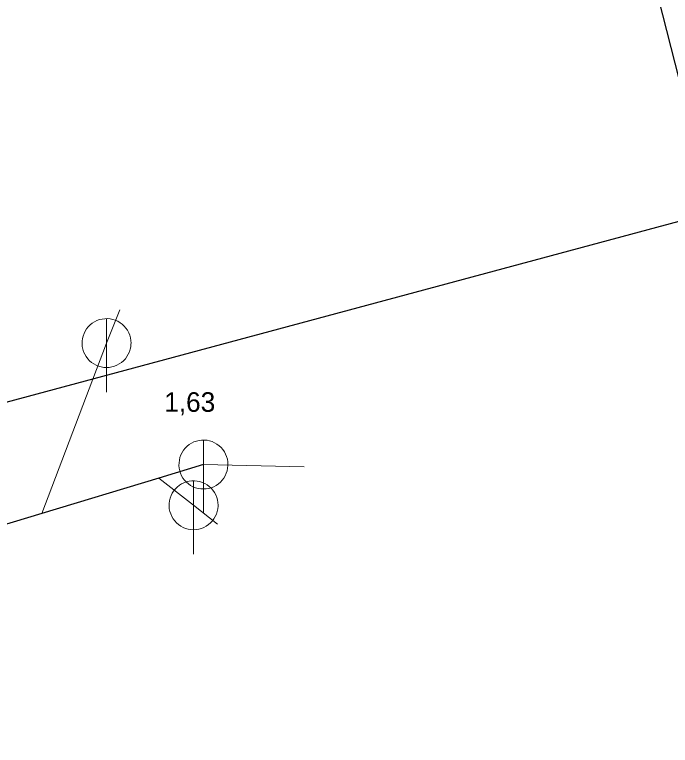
# Model space of a CAD drawing. Extents: x -682839 to -682312, y -994645 to -993949.
# Drawn here: x -682713.06 to -682686.28, y -994200.26 to -994170.41 of the extents above; entities that cross this region are included whole.
import ezdxf

# ---------------------------------------------------------------- set-up
doc = ezdxf.new("R2010")
doc.units = 0
doc.header["$LTSCALE"] = 0.4
doc.layers.add('1', color=7, linetype='Continuous')
for name, color, linetype, lineweight in [('11', 7, 'Continuous', 13), ('14', 7, 'Continuous', 25), ('17', 7, 'Continuous', 25), ('22', 7, 'Continuous', 13)]:
    doc.layers.add(name, color=color, linetype=linetype, lineweight=lineweight)

msp = doc.modelspace()

# ---------------------------------------------------------------- linework, layer by layer
at = {"layer": '11'}
for p, q in [((-682708.759, -994182.471), (-682709.306, -994183.829)), ((-682709.306, -994183.829), (-682711.949, -994190.789)), ((-682701.239, -994188.879), (-682705.35, -994188.789)), ((-682705.753, -994190.453), (-682707.17, -994189.34)), ((-682704.778, -994191.219), (-682705.753, -994190.453))]:
    msp.add_line(p, q, dxfattribs=at)
at = {"layer": '14'}
msp.add_line((-682684.149, -994180.09), (-682694.03, -994140.85), dxfattribs=at)
msp.add_lwpolyline([(-682705.35, -994188.789), (-682707.17, -994189.34), (-682711.949, -994190.789), (-682724.48, -994194.579), (-682732.44, -994196.989)], dxfattribs=at)
at = {"layer": '17'}
msp.add_line((-682765.462, -994200.262), (-682682.065, -994177.804), dxfattribs=at)
at = {"layer": '22'}
for p, q in [((-682709.306, -994185.829), (-682709.305, -994182.829)), ((-682705.35, -994190.789), (-682705.349, -994187.789)), ((-682705.753, -994192.453), (-682705.752, -994189.453))]:
    msp.add_line(p, q, dxfattribs=at)
for points in [[(-682708.306, -994183.829), (-682708.311, -994183.72), (-682708.329, -994183.612), (-682708.359, -994183.506), (-682708.399, -994183.405), (-682708.451, -994183.308), (-682708.513, -994183.218), (-682708.585, -994183.135), (-682708.665, -994183.061), (-682708.753, -994182.995), (-682708.847, -994182.94), (-682708.947, -994182.895), (-682709.052, -994182.862), (-682709.159, -994182.84), (-682709.268, -994182.83), (-682709.378, -994182.832), (-682709.486, -994182.846), (-682709.593, -994182.871), (-682709.696, -994182.908), (-682709.794, -994182.957), (-682709.886, -994183.015), (-682709.972, -994183.084), (-682710.049, -994183.161), (-682710.118, -994183.247), (-682710.177, -994183.339), (-682710.225, -994183.437), (-682710.262, -994183.54), (-682710.288, -994183.647), (-682710.302, -994183.755), (-682710.305, -994183.865), (-682710.295, -994183.974), (-682710.274, -994184.081), (-682710.24, -994184.185), (-682710.196, -994184.285), (-682710.141, -994184.38), (-682710.075, -994184.468), (-682710.001, -994184.548), (-682709.918, -994184.62), (-682709.828, -994184.682), (-682709.732, -994184.734), (-682709.63, -994184.775), (-682709.525, -994184.805), (-682709.417, -994184.823), (-682709.307, -994184.829), (-682709.198, -994184.823), (-682709.09, -994184.805), (-682708.985, -994184.776), (-682708.883, -994184.735), (-682708.786, -994184.683), (-682708.696, -994184.621), (-682708.613, -994184.55), (-682708.538, -994184.47), (-682708.473, -994184.382), (-682708.417, -994184.288), (-682708.373, -994184.188), (-682708.339, -994184.084), (-682708.317, -994183.976), (-682708.307, -994183.867)], [(-682704.35, -994188.789), (-682704.355, -994188.68), (-682704.373, -994188.572), (-682704.403, -994188.466), (-682704.443, -994188.365), (-682704.495, -994188.268), (-682704.557, -994188.178), (-682704.629, -994188.095), (-682704.709, -994188.021), (-682704.797, -994187.955), (-682704.891, -994187.9), (-682704.991, -994187.855), (-682705.096, -994187.822), (-682705.203, -994187.8), (-682705.312, -994187.79), (-682705.422, -994187.792), (-682705.53, -994187.806), (-682705.637, -994187.831), (-682705.74, -994187.868), (-682705.838, -994187.917), (-682705.93, -994187.975), (-682706.016, -994188.044), (-682706.093, -994188.121), (-682706.162, -994188.207), (-682706.221, -994188.299), (-682706.269, -994188.397), (-682706.306, -994188.5), (-682706.332, -994188.607), (-682706.346, -994188.715), (-682706.349, -994188.825), (-682706.339, -994188.934), (-682706.318, -994189.041), (-682706.284, -994189.145), (-682706.24, -994189.245), (-682706.185, -994189.34), (-682706.119, -994189.428), (-682706.045, -994189.508), (-682705.962, -994189.58), (-682705.872, -994189.642), (-682705.776, -994189.694), (-682705.674, -994189.735), (-682705.569, -994189.765), (-682705.461, -994189.783), (-682705.351, -994189.789), (-682705.242, -994189.783), (-682705.134, -994189.765), (-682705.029, -994189.736), (-682704.927, -994189.695), (-682704.83, -994189.643), (-682704.74, -994189.581), (-682704.657, -994189.51), (-682704.582, -994189.43), (-682704.517, -994189.342), (-682704.461, -994189.248), (-682704.417, -994189.148), (-682704.383, -994189.044), (-682704.361, -994188.936), (-682704.351, -994188.827)], [(-682704.753, -994190.453), (-682704.758, -994190.344), (-682704.776, -994190.236), (-682704.806, -994190.13), (-682704.846, -994190.029), (-682704.898, -994189.932), (-682704.96, -994189.842), (-682705.032, -994189.759), (-682705.112, -994189.685), (-682705.2, -994189.619), (-682705.294, -994189.564), (-682705.394, -994189.519), (-682705.499, -994189.486), (-682705.606, -994189.464), (-682705.715, -994189.454), (-682705.825, -994189.456), (-682705.933, -994189.47), (-682706.04, -994189.495), (-682706.143, -994189.532), (-682706.241, -994189.581), (-682706.333, -994189.639), (-682706.419, -994189.708), (-682706.496, -994189.785), (-682706.565, -994189.871), (-682706.624, -994189.963), (-682706.672, -994190.061), (-682706.709, -994190.164), (-682706.735, -994190.271), (-682706.749, -994190.379), (-682706.752, -994190.489), (-682706.742, -994190.598), (-682706.721, -994190.705), (-682706.687, -994190.809), (-682706.643, -994190.909), (-682706.588, -994191.004), (-682706.522, -994191.092), (-682706.448, -994191.172), (-682706.365, -994191.244), (-682706.275, -994191.306), (-682706.179, -994191.358), (-682706.077, -994191.399), (-682705.972, -994191.429), (-682705.864, -994191.447), (-682705.754, -994191.453), (-682705.645, -994191.447), (-682705.537, -994191.429), (-682705.432, -994191.4), (-682705.33, -994191.359), (-682705.233, -994191.307), (-682705.143, -994191.245), (-682705.06, -994191.174), (-682704.985, -994191.094), (-682704.92, -994191.006), (-682704.864, -994190.912), (-682704.82, -994190.812), (-682704.786, -994190.708), (-682704.764, -994190.6), (-682704.754, -994190.491)]]:
    msp.add_lwpolyline(points, close=True, dxfattribs=at)

# ---------------------------------------------------------------- texts
at = {"layer": '1'}
msp.add_text('1,63', height=0.8, dxfattribs=at).set_placement((-682706.949, -994186.637))

doc.saveas('drawing.dxf')
